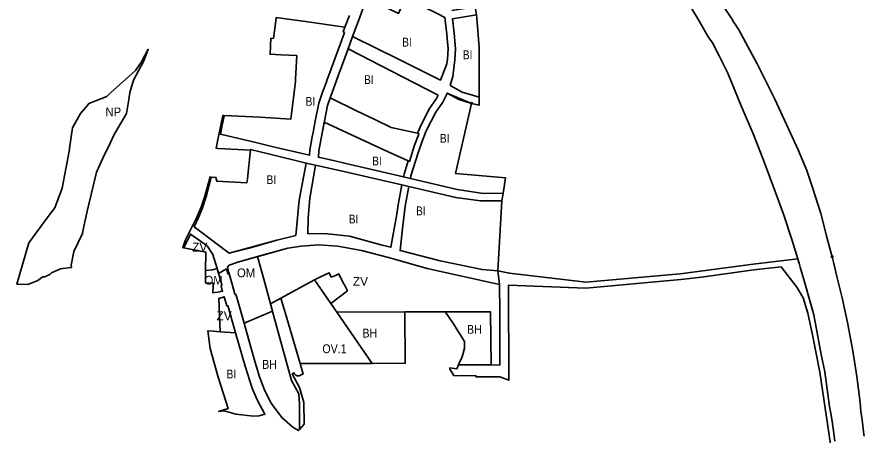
# Model space of a CAD drawing. Extents: x -650276 to -642489, y -1074311 to -1066658.
# Drawn here: x -646120 to -644974, y -1070212 to -1069647 of the extents above; entities that cross this region are included whole.
import ezdxf

# ---------------------------------------------------------------- set-up
doc = ezdxf.new("R2010")
doc.units = 0
doc.header["$LTSCALE"] = 4.8
doc.header["$PDMODE"] = 32
doc.header["$PDSIZE"] = 2.4
for name, color, linetype, lineweight in [('1', 7, 'Continuous', 35), ('11', 7, 'Continuous', 35), ('12', 7, 'Continuous', 35), ('15', 7, 'Continuous', 35), ('2', 7, 'Continuous', 35), ('24', 7, 'Continuous', 35), ('40', 7, 'Continuous', 35), ('48', 7, 'Continuous', 35)]:
    doc.layers.add(name, color=color, linetype=linetype, lineweight=lineweight)
doc.layers.add('62', color=7, linetype='Continuous')

msp = doc.modelspace()

# ---------------------------------------------------------------- linework, layer by layer
at = {"layer": '1'}
for points in [[(-645772.853, -1070049.868), (-645774.423, -1070044.167), (-645783.063, -1070047.855), (-645812.76, -1070060.53)], [(-645737.756, -1070204.389), (-645737.624, -1070169.544), (-645738.79, -1070156.281), (-645748.62, -1070137.889), (-645772.853, -1070049.868)], [(-645812.76, -1070060.53), (-645804.52, -1070089.63), (-645797.66, -1070113.88), (-645791.72, -1070133.09), (-645784.83, -1070151.9), (-645784.83, -1070151.9)], [(-645784.83, -1070151.9), (-645776.26, -1070168.94), (-645761.78, -1070188.29), (-645746.73, -1070201.04), (-645739.12, -1070205.9), (-645737.756, -1070204.389)]]:
    msp.add_lwpolyline(points, dxfattribs=at)
for points in [[(-645639.638, -1070114.895), (-645594.733, -1070114.868), (-645595.2, -1070045.403), (-645687.31, -1070045.724)], [(-645522.587, -1070116.952), (-645478.664, -1070117.114), (-645479.429, -1070045.409), (-645540.433, -1070045.752), (-645530.3, -1070060.08), (-645514.49, -1070085.4), (-645514.56, -1070090.91), (-645514.61, -1070094.35), (-645517.02, -1070103.08), (-645518.35, -1070106.87), (-645521.73, -1070114.83)]]:
    msp.add_lwpolyline(points, close=True, dxfattribs=at)
at = {"layer": '11'}
msp.add_lwpolyline([(-645639.638, -1070114.895), (-645687.31, -1070045.724), (-645717.36, -1070002.12), (-645762.868, -1070026.606), (-645757.215, -1070045.97), (-645737.075, -1070114.955)], close=True, dxfattribs=at)
at = {"layer": '12'}
for points in [[(-645794.679, -1069970.596), (-645821, -1069978), (-645833, -1069982), (-645835, -1069985), (-645833.32, -1069991.86)], [(-645777.143, -1070034.287), (-645786.238, -1070001.251), (-645794.679, -1069970.596)], [(-645833.32, -1069991.86), (-645828.9, -1070007.76), (-645825.08, -1070021.52)], [(-645825.08, -1070021.52), (-645823.76, -1070021.67), (-645822.549, -1070025.948), (-645812.76, -1070060.53), (-645783.063, -1070047.855), (-645774.423, -1070044.167), (-645777.143, -1070034.287)]]:
    msp.add_lwpolyline(points, dxfattribs=at)
msp.add_lwpolyline([(-645855.17, -1070019.44), (-645852.36, -1070019.01), (-645852.33, -1070019.2), (-645845.37, -1070018.12), (-645845.14, -1070018.08), (-645845.17, -1070017.91), (-645841.89, -1070017.42), (-645842.238, -1070016.251), (-645843.94, -1070010.6), (-645843, -1070009), (-645842.8, -1070008.59), (-645843.22, -1070007.12), (-645849.1, -1069986.42), (-645855.54, -1069988.24), (-645864.77, -1069989.26), (-645864.97, -1070006.16), (-645854.42, -1070006.47), (-645854.65, -1070010.44)], close=True, dxfattribs=at)
at = {"layer": '15'}
for points in [[(-645638.203, -1069597.8), (-645626.95, -1069602.91), (-645621.56, -1069605.68), (-645594.58, -1069619.56), (-645594.818, -1069620.139), (-645550.62, -1069642.176), (-645541.064, -1069647.092)], [(-645670.23, -1069644.67), (-645676.34, -1069660.28), (-645678.73, -1069666.78), (-645676.984, -1069667.634), (-645682.314, -1069682.197), (-645689.959, -1069703.082), (-645696.794, -1069721.756), (-645700.87, -1069732.593), (-645701.968, -1069735.514), (-645706.663, -1069747.998), (-645711.852, -1069763.14), (-645716.534, -1069787.483), (-645719.436, -1069802.573), (-645720.632, -1069808.792), (-645722.474, -1069819.017), (-645723.777, -1069826.243), (-645724.25, -1069833.353), (-645775.326, -1069821.576), (-645802.431, -1069814.987), (-645804.657, -1069814.455), (-645844.737, -1069804.875), (-645842.728, -1069795.578), (-645842.648, -1069795.17), (-645839.721, -1069780.247), (-645839.658, -1069779.835), (-645841.41, -1069779.76), (-645844.57, -1069795.07), (-645848.35, -1069812.09), (-645850.63, -1069824.09), (-645847.62, -1069824.26), (-645812.18, -1069826.3), (-645804.28, -1069826.76), (-645804.185, -1069825.84), (-645777.852, -1069832.241), (-645729.006, -1069844.136), (-645716.277, -1069847.01), (-645677.849, -1069855.3), (-645599.271, -1069873.685), (-645589.84, -1069875.892), (-645526.451, -1069890.745), (-645492.842, -1069895), (-645464.288, -1069895.362), (-645462.303, -1069885.376), (-645492, -1069885), (-645524.43, -1069879.921), (-645587.785, -1069865.117), (-645597.216, -1069862.91), (-645675.369, -1069844.625), (-645689.909, -1069841.272), (-645712.203, -1069836.131), (-645711.644, -1069827.736), (-645710.289, -1069820.217), (-645708.633, -1069811.027), (-645700.028, -1069766.286), (-645696.517, -1069756.039), (-645695.176, -1069752.125), (-645689.63, -1069737.38), (-645685.351, -1069726.002), (-645671.999, -1069689.523), (-645665.961, -1069673.028), (-645658.119, -1069651.601), (-645645.715, -1069618.085)], [(-645530.797, -1069648.949), (-645498.61, -1069643.729), (-645500.137, -1069632.833), (-645531.753, -1069637.96)], [(-645541.064, -1069647.092), (-645538.744, -1069669.644), (-645538.15, -1069675.537)], [(-645533.953, -1069739.166), (-645530.534, -1069726.969), (-645527.824, -1069704.697), (-645526.643, -1069689.732), (-645528.772, -1069668.628), (-645530.797, -1069648.949)], [(-645538.15, -1069675.537), (-645536.707, -1069689.842), (-645537.8, -1069703.696), (-645538.579, -1069710.102), (-645546.93, -1069731.98), (-645602.91, -1069703.88), (-645665.961, -1069673.028), (-645671.999, -1069689.523), (-645655.45, -1069698.05), (-645614.28, -1069719.27), (-645550.184, -1069752.242)], [(-645539.126, -1069751.764), (-645538.096, -1069749.446), (-645522.277, -1069758.205), (-645504.976, -1069763.332), (-645495, -1069766), (-645495, -1069754.815), (-645518, -1069748), (-645533.953, -1069739.166)], [(-645587.785, -1069865.117), (-645587.052, -1069861.272), (-645577.497, -1069830.237), (-645572.56, -1069815.628), (-645566.341, -1069800.49), (-645553.635, -1069775.217), (-645544.108, -1069761.733), (-645539.126, -1069751.764)], [(-645550.184, -1069752.242), (-645552.437, -1069756.749), (-645561.956, -1069770.224), (-645573.652, -1069793.487)], [(-645573.652, -1069793.487), (-645575.153, -1069796.472), (-645578.134, -1069803.73)], [(-645578.134, -1069803.73), (-645576.34, -1069804.13), (-645577.52, -1069807.26), (-645582.31, -1069820.05), (-645589.23, -1069841.89), (-645590.964, -1069841.09)], [(-645590.964, -1069841.09), (-645596.458, -1069858.935), (-645597.216, -1069862.91), (-645587.785, -1069865.117)], [(-645061.76, -1069981.21), (-645064.052, -1069973.429), (-645124.233, -1069980.695), (-645222.809, -1069993.701), (-645350.784, -1070005.227), (-645453.852, -1069992.968), (-645469.701, -1069990.011), (-645467.472, -1070008.38), (-645467.068, -1070044.959), (-645466.96, -1070117.157), (-645478.664, -1070117.114), (-645522.587, -1070116.952), (-645524.82, -1070122.48), (-645534.63, -1070121.09), (-645534.7, -1070122.95), (-645529.17, -1070131.4), (-645499.276, -1070131.652), (-645499.142, -1070133.293), (-645466.862, -1070133.219), (-645454.881, -1070137.836), (-645455.073, -1070009.111), (-645350.591, -1070013.242), (-645221.99, -1070001.66), (-645194.003, -1069998.417), (-645123.206, -1069988.629), (-645086.484, -1069984.195), (-645065.235, -1070011.695)], [(-645013.77, -1070220.04), (-645016.92, -1070196.32), (-645018.56, -1070184.92), (-645021.14, -1070173.07), (-645027.49, -1070126.56), (-645032.21, -1070102.73), (-645042.27, -1070049.23), (-645047.28, -1070031.83), (-645054.73, -1070004.56), (-645060.612, -1069985.022), (-645061.76, -1069981.21)], [(-645065.235, -1070011.695), (-645056.555, -1070026.163), (-645050.293, -1070047.035), (-645043.92, -1070076.344), (-645034.122, -1070126.616), (-645004.791, -1070324.889), (-645004.523, -1070326.697)], [(-645757.215, -1070045.97), (-645762.868, -1070026.606), (-645777.143, -1070034.287), (-645772.853, -1070049.868), (-645748.62, -1070137.889)], [(-645737.63, -1070147.39), (-645747.67, -1070129.14), (-645745.29, -1070127.83), (-645744.73, -1070129), (-645743.87, -1070130.15), (-645742.67, -1070131.07), (-645741.83, -1070131.53), (-645740.89, -1070131.8), (-645739.41, -1070131.93), (-645738.41, -1070131.78), (-645737.48, -1070131.45), (-645734.77, -1070130.18), (-645732.91, -1070129.5), (-645737.075, -1070114.955), (-645757.215, -1070045.97)], [(-645748.62, -1070137.889), (-645738.79, -1070156.281), (-645737.624, -1070169.544), (-645737.756, -1070204.389)], [(-645737.756, -1070204.389), (-645731.3, -1070197.24), (-645731.94, -1070167.87), (-645737.63, -1070147.39)]]:
    msp.add_lwpolyline(points, dxfattribs=at)
msp.add_lwpolyline([(-645712.222, -1069954.725), (-645686.147, -1069956.306), (-645654.145, -1069962.232), (-645617.403, -1069971.714), (-645565.133, -1069986.508), (-645467.472, -1070008.38), (-645469.701, -1069990.011), (-645490.814, -1069988.074), (-645547.4, -1069976.382), (-645601.753, -1069962.317), (-645598.491, -1069932.472), (-645596.463, -1069914.335), (-645594.866, -1069902.242), (-645589.84, -1069875.892), (-645599.271, -1069873.685), (-645604.424, -1069900.701), (-645606.07, -1069913.163), (-645614.072, -1069957.797), (-645625.979, -1069954.92), (-645670.325, -1069943.002), (-645699.889, -1069939.714), (-645726.542, -1069939.398), (-645726.131, -1069918.457), (-645723.668, -1069891.356), (-645716.277, -1069847.01), (-645729.006, -1069844.136), (-645738.039, -1069894.231), (-645742.967, -1069941.862), (-645768.424, -1069948.431), (-645833, -1069966), (-645880.431, -1069930.3), (-645874.219, -1069917.496), (-645869.262, -1069905.935), (-645863.95, -1069889.468), (-645857.289, -1069863.338), (-645857.204, -1069862.954), (-645858.78, -1069862.84), (-645865.78, -1069888.76), (-645870.89, -1069903.5), (-645876.15, -1069916.47), (-645892.09, -1069947.98), (-645895.66, -1069958.42), (-645894.25, -1069958.7), (-645885.422, -1069940.184), (-645862.782, -1069955.809), (-645854.81, -1069967.927), (-645849.1, -1069986.42), (-645847.14, -1069993.34), (-645836.64, -1069987.18), (-645834.65, -1069994.21), (-645833.32, -1069991.86), (-645835, -1069985), (-645833, -1069982), (-645821, -1069978), (-645753.706, -1069959.071), (-645735.532, -1069956.306)], close=True, dxfattribs=at)
at = {"layer": '2'}
for p, q in [((-645526.643, -1069689.732), (-645527.824, -1069704.697)), ((-645701.968, -1069735.514), (-645700.87, -1069732.593))]:
    msp.add_line(p, q, dxfattribs=at)
for points in [[(-645645.715, -1069618.085), (-645658.119, -1069651.601), (-645665.961, -1069673.028), (-645602.91, -1069703.88), (-645546.93, -1069731.98), (-645538.579, -1069710.102)], [(-645538.15, -1069675.537), (-645538.744, -1069669.644), (-645541.064, -1069647.092), (-645550.62, -1069642.176), (-645594.818, -1069620.139), (-645603.7, -1069641.75), (-645630.93, -1069628.84), (-645629.78, -1069626.03), (-645645.715, -1069618.085)], [(-645495, -1069744), (-645495, -1069688), (-645498, -1069648), (-645498.61, -1069643.729), (-645530.793, -1069648.948), (-645530.757, -1069649.336)], [(-645700.87, -1069732.593), (-645696.794, -1069721.756), (-645689.959, -1069703.082), (-645682.314, -1069682.197), (-645676.984, -1069667.634), (-645678.73, -1069666.78), (-645676.34, -1069660.28), (-645726.57, -1069653.22), (-645769.264, -1069647.213), (-645769.36, -1069648), (-645773.02, -1069675.47), (-645776.45, -1069675.26), (-645777.62, -1069696.85), (-645763.24, -1069697.58), (-645741.43, -1069698.68), (-645743.01, -1069730.72), (-645743.36, -1069733.7), (-645749.48, -1069784.61), (-645791.2, -1069781.92), (-645839.658, -1069779.835)], [(-645530.757, -1069649.336), (-645528.772, -1069668.628), (-645526.643, -1069689.732)], [(-645538.579, -1069710.102), (-645537.8, -1069703.696), (-645536.707, -1069689.842), (-645538.15, -1069675.537)], [(-645550.184, -1069752.242), (-645614.28, -1069719.27), (-645655.45, -1069698.05), (-645671.999, -1069689.523), (-645685.351, -1069726.002), (-645689.63, -1069737.38), (-645695.176, -1069752.125), (-645696.517, -1069756.039), (-645660.57, -1069773.31)], [(-645527.824, -1069704.697), (-645530.534, -1069726.969), (-645533.953, -1069739.166)], [(-645716.534, -1069787.483), (-645711.852, -1069763.14), (-645706.663, -1069747.998), (-645701.968, -1069735.514)], [(-645533.953, -1069739.166), (-645518, -1069748), (-645495, -1069754.815), (-645495, -1069744)], [(-645574.28, -1069794.735), (-645573.652, -1069793.487), (-645561.956, -1069770.224), (-645552.437, -1069756.749), (-645550.184, -1069752.242)], [(-645504.976, -1069763.332), (-645538.096, -1069749.446), (-645539.126, -1069751.764), (-645544.108, -1069761.733)], [(-645577.497, -1069830.237), (-645587.052, -1069861.272), (-645587.785, -1069865.117), (-645524.43, -1069879.921), (-645492, -1069885), (-645462.303, -1069885.376), (-645459.312, -1069864.01), (-645526.374, -1069858.055), (-645527, -1069858), (-645504.976, -1069763.332)], [(-645544.108, -1069761.733), (-645553.635, -1069775.217), (-645566.341, -1069800.49), (-645572.56, -1069815.628), (-645577.497, -1069830.237)], [(-645839.658, -1069779.835), (-645839.721, -1069780.247), (-645842.648, -1069795.17)], [(-645660.57, -1069773.31), (-645635.79, -1069785.23), (-645613.84, -1069795.78), (-645578.134, -1069803.731), (-645576.185, -1069798.985)], [(-645722.474, -1069819.017), (-645720.632, -1069808.792), (-645719.436, -1069802.573), (-645716.534, -1069787.483)], [(-645590.964, -1069841.09), (-645623.75, -1069825.97), (-645704.355, -1069788.786), (-645708.633, -1069811.027), (-645710.289, -1069820.217), (-645711.644, -1069827.736), (-645712.203, -1069836.131)], [(-645842.648, -1069795.17), (-645842.728, -1069795.578), (-645844.737, -1069804.875), (-645804.657, -1069814.455)], [(-645576.185, -1069798.985), (-645575.153, -1069796.472), (-645574.28, -1069794.735)], [(-645804.657, -1069814.455), (-645802.431, -1069814.987), (-645775.326, -1069821.576), (-645724.25, -1069833.353)], [(-645724.25, -1069833.353), (-645723.777, -1069826.243), (-645722.474, -1069819.017)], [(-645712.203, -1069836.131), (-645689.909, -1069841.272), (-645675.369, -1069844.625), (-645597.216, -1069862.91)], [(-645597.216, -1069862.91), (-645596.458, -1069858.935), (-645590.964, -1069841.09)]]:
    msp.add_lwpolyline(points, dxfattribs=at)
for points in [[(-645806, -1069959), (-645768.424, -1069948.431), (-645742.967, -1069941.862), (-645738.039, -1069894.231), (-645729.006, -1069844.136), (-645777.852, -1069832.241), (-645804.185, -1069825.84), (-645808.28, -1069865.39), (-645808.84, -1069870.75), (-645849.79, -1069868.4), (-645850.92, -1069863.41), (-645857.204, -1069862.954), (-645857.289, -1069863.338), (-645863.95, -1069889.468), (-645869.262, -1069905.935), (-645874.219, -1069917.496), (-645880.431, -1069930.3), (-645833, -1069966)], [(-645606.07, -1069913.163), (-645604.424, -1069900.701), (-645599.271, -1069873.685), (-645677.849, -1069855.3), (-645716.277, -1069847.01), (-645723.668, -1069891.356), (-645726.131, -1069918.457), (-645726.542, -1069939.398), (-645699.889, -1069939.714), (-645670.325, -1069943.002), (-645625.979, -1069954.92), (-645614.072, -1069957.797)], [(-645589.84, -1069875.892), (-645594.866, -1069902.242), (-645598.491, -1069932.472), (-645601.753, -1069962.317), (-645547.4, -1069976.382), (-645490.814, -1069988.074), (-645469.701, -1069990.011), (-645469.701, -1069990.011), (-645464.288, -1069895.362), (-645492.842, -1069895), (-645526.451, -1069890.745)], [(-645792.37, -1070186.01), (-645784.51, -1070183.77), (-645795.07, -1070164.26), (-645801.99, -1070148.51), (-645811.48, -1070118.65), (-645824.28, -1070073.67), (-645845.01, -1070072.12), (-645854.25, -1070071.4), (-645861.74, -1070070.95), (-645858.53, -1070094.64), (-645847.88, -1070133.4), (-645834.31, -1070176.15), (-645847.2, -1070180.14), (-645839.82, -1070178.94), (-645824.12, -1070183.63), (-645799.91, -1070186.32)]]:
    msp.add_lwpolyline(points, close=True, dxfattribs=at)
msp.add_point((-645504.976, -1069763.332), dxfattribs=at)
at = {"layer": '24'}
for points in [[(-645322.13, -1069447.96), (-645309.62, -1069467.79), (-645303.57, -1069480.49), (-645268.57, -1069533.23), (-645242.75, -1069570.26), (-645230.42, -1069597.39), (-645227.27, -1069602.68), (-645225.7, -1069605.32), (-645214.76, -1069622.37), (-645198.41, -1069650.49), (-645185.17, -1069673.38), (-645179.12, -1069681.3), (-645170.3, -1069698.91), (-645158.43, -1069722.61), (-645153.44, -1069734.71), (-645140.27, -1069766.68), (-645123.84, -1069805.38), (-645108.74, -1069843.58), (-645094.42, -1069882.65), (-645083.31, -1069913.37), (-645071.53, -1069948.89), (-645063.96, -1069973.73), (-645063.23, -1069976.2), (-645062.57, -1069978.46)], [(-645017.46, -1069970.61), (-645018.28, -1069967.49), (-645024.45, -1069944.43), (-645032.85, -1069912.07), (-645043.5, -1069878.37), (-645051.78, -1069854.2), (-645063.26, -1069825.99), (-645095.1, -1069757.62), (-645118.98, -1069710.08), (-645143.56, -1069664.05), (-645148.8, -1069656.1), (-645150.3, -1069653.84), (-645153.33, -1069649.24), (-645166.67, -1069629)], [(-644996.88, -1070059.73), (-645004.02, -1070026.44), (-645010.54, -1069999.3), (-645015.548, -1069978.177), (-645016.01, -1069976.23), (-645016.89, -1069972.82), (-645017.46, -1069970.61)], [(-645062.57, -1069978.46), (-645061.76, -1069981.21), (-645060.612, -1069985.022), (-645054.73, -1070004.56), (-645047.28, -1070031.83), (-645042.27, -1070049.23), (-645032.21, -1070102.73), (-645027.49, -1070126.56), (-645021.14, -1070173.07), (-645018.56, -1070184.92), (-645016.92, -1070196.32), (-645013.77, -1070220.04)], [(-644974.29, -1070213.17), (-644974.49, -1070210.98), (-644976.94, -1070191.41), (-644978.49, -1070180.05), (-644979.57, -1070167.9), (-644984.21, -1070132.81), (-644989.62, -1070097.79), (-644996.88, -1070059.73)]]:
    msp.add_lwpolyline(points, dxfattribs=at)
msp.add_point((-645017.46, -1069970.61), dxfattribs=at)
at = {"layer": '40'}
for points in [[(-645849.1, -1069986.42), (-645854.81, -1069967.927), (-645862.782, -1069955.809), (-645885.422, -1069940.184), (-645894.25, -1069958.7), (-645864.48, -1069964.53), (-645864.77, -1069989.26), (-645855.54, -1069988.24)], [(-645595.2, -1070045.403), (-645479.429, -1070045.409), (-645478.664, -1070117.114), (-645466.96, -1070117.157), (-645467.068, -1070044.959), (-645467.472, -1070008.38), (-645565.133, -1069986.508), (-645617.403, -1069971.714), (-645654.145, -1069962.232), (-645686.147, -1069956.306), (-645712.222, -1069954.725), (-645735.532, -1069956.306), (-645753.706, -1069959.071), (-645794.679, -1069970.596), (-645786.238, -1070001.251), (-645777.143, -1070034.287), (-645762.868, -1070026.606), (-645717.36, -1070002.12), (-645710.43, -1069998.39), (-645697.59, -1069992.31), (-645694.8, -1069998.22), (-645689.84, -1069996.37), (-645684.59, -1069993.87), (-645677.65, -1070007.66), (-645677.02, -1070008.93), (-645675.24, -1070012.51), (-645673.1, -1070016.78), (-645695.39, -1070034), (-645687.31, -1070045.724)], [(-645834.8, -1070036.71), (-645835.91, -1070037.31), (-645839.64, -1070024.9), (-645847.08, -1070027.09), (-645845.01, -1070072.12), (-645824.28, -1070073.67), (-645824.28, -1070073.67)]]:
    msp.add_lwpolyline(points, close=True, dxfattribs=at)
at = {"layer": '48'}
msp.add_lwpolyline([(-646050.68, -1069985.78), (-646046.28, -1069985.18), (-646046.63, -1069982.04), (-646043.2, -1069963.46), (-646031.24, -1069939.45), (-646030.62, -1069936.3), (-646027.3, -1069919.47), (-646024.41, -1069907.23), (-646012.37, -1069856.22), (-646003.18, -1069836.56), (-645993.96, -1069817.23), (-645989.01, -1069806.25), (-645983.89, -1069797.86), (-645971.7, -1069777.05), (-645968.78, -1069758.13), (-645967.35, -1069748.81), (-645962.48, -1069732.04), (-645948.22, -1069705.79), (-645942.41, -1069690.26), (-645951.52, -1069707.28), (-645959.63, -1069718.95), (-645993.22, -1069749.24), (-645998.57, -1069754.06), (-646022.72, -1069763.59), (-646025.11, -1069766.63), (-646034.02, -1069777.19), (-646044.94, -1069796.35), (-646048.71, -1069823.79), (-646049, -1069825.93), (-646058.71, -1069877.82), (-646068.5, -1069904.5), (-646077.78, -1069916.11), (-646104.04, -1069951.75), (-646119.95, -1070007.73), (-646105.35, -1070008.18), (-646091.87, -1070002.66), (-646084.39, -1069997.53), (-646083.67, -1069998.4), (-646075.69, -1069994.68), (-646073.1, -1069992.61), (-646060.94, -1069987.19)], close=True, dxfattribs=at)

# ---------------------------------------------------------------- texts
at = {"layer": '62'}
for s, width, p in [('BI', 0.85, (-645598.928, -1069686.593)), ('BI', 0.85, (-645516.874, -1069703.638)), ('BI', 0.85, (-645650.447, -1069737.266)), ('BI', 0.85, (-645729.524, -1069766.68)), ('NP', 0.95, (-646000.15, -1069780.972)), ('BI', 0.85, (-645547.874, -1069816.638)), ('BI', 0.85, (-645639.447, -1069847.266)), ('BI', 0.85, (-645782.319, -1069872.497)), ('BI', 0.85, (-645580.138, -1069914.734)), ('BI', 0.85, (-645671.138, -1069925.734)), ('OM', 0.95, (-645822.28, -1069998.561)), ('OM', 0.95, (-645866.28, -1070008.561)), ('BH', 0.9, (-645652.699, -1070079.977)), ('BH', 0.9, (-645511.328, -1070074.977)), ('OV.1', 0.9, (-645706.926, -1070101.134)), ('BH', 0.9, (-645788.337, -1070122.32)), ('BI', 0.85, (-645836.337, -1070135.32))]:
    msp.add_text(s, height=12, dxfattribs=dict(at, width=width)).set_placement(p)
for p in [(-645883.022, -1069963.776), (-645665.601, -1070009.978), (-645850.022, -1070056.776)]:
    msp.add_text('ZV', height=12, dxfattribs=at).set_placement(p)

doc.saveas('drawing.dxf')
